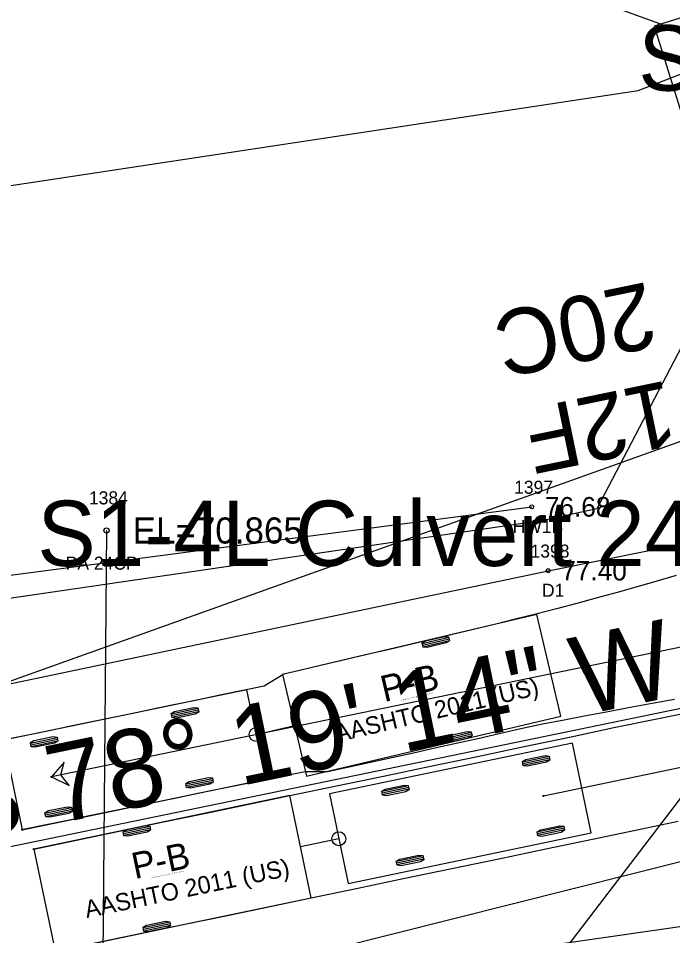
# Model space of a CAD drawing. Extents: x 2500794 to 2511032, y 910653 to 917533.
# Drawn here: x 2506003.2 to 2506053.3, y 913947.8 to 914018.1 of the extents above; entities that cross this region are included whole.
import ezdxf

# ---------------------------------------------------------------- set-up
doc = ezdxf.new("R2010")
doc.units = 0
for name, color, linetype in [('Default', 7, 'Continuous'), ('RD_EX_Bridge', 7, 'Continuous'), ('RD_EX_Bridge_txCode', 7, 'Continuous'), ('RD_EX_DR_Pipe', 7, 'Continuous'), ('RD_EX_DR_Pipe_txCode', 7, 'Continuous'), ('RD_EX_Driveway', 7, 'Continuous'), ('RD_EX_Driveway_txCode', 7, 'Continuous'), ('RD_EX_H2O', 7, 'Continuous'), ('RD_EX_H2O_txCode', 7, 'Continuous'), ('RD_EX_RW', 7, 'Continuous'), ('RD_EX_TX_Bridge_ELEV', 7, 'Continuous'), ('RD_EX_TX_Driveway_ELEV', 7, 'Continuous'), ('RD_EX_Wall', 7, 'Continuous'), ('RD_HC_Cl', 7, 'Continuous'), ('RD_HC_CL_Rel', 7, 'Continuous'), ('RD_HC_Data', 7, 'Continuous'), ('RD_HC_Data_Rel', 7, 'Continuous'), ('RD_PD_ALT1_TnTmp', 7, 'Continuous'), ('RD_PD_CstnLmt', 7, 'Continuous'), ('RD_PD_Detour', 7, 'Continuous'), ('RD_PD_Signals', 7, 'Continuous'), ('RD_SMD_Locator', 7, 'Continuous'), ('RD_TX_Pipe_ElevEX', 7, 'Continuous')]:
    doc.layers.add(name, color=color, linetype=linetype)

# ---------------------------------------------------------------- blocks, each defined once
blk = doc.blocks.new('POINT_DISPLAY')
at = {"layer": 'Default'}
blk.add_line((0, 0), (0, 0), dxfattribs=at)
blk = doc.blocks.new('Non-Wetland Waters (Tributaries)')
at = {"layer": 'Default'}
blk.add_lwpolyline([(636463.424, 232143.109), (636471.33, 232152.976), (636485.289, 232157.041), (636505.816, 232154.48), (636536.861, 232159.182), (636555.919, 232166.539), (636568.556, 232167.887)], dxfattribs=at)

msp = doc.modelspace()

# ---------------------------------------------------------------- linework, layer by layer
at = {"layer": 'RD_EX_Bridge'}
msp.add_line((2505983.467, 913972.927), (2506042.488, 913980.668), dxfattribs=at)
at = {"layer": 'RD_EX_DR_Pipe'}
msp.add_line((2506009.966, 913978.856), (2506009.594, 913936.08), dxfattribs=at)
at = {"layer": 'RD_EX_Driveway'}
for points in [[(2505985.767, 913963.589), (2506043.743, 913975.78), (2506109.597, 913989.049), (2506154.744, 914000.103)], [(2505819.536, 913956.764), (2505827.101, 913947.153), (2505840.353, 913935.262), (2505856.8, 913926.646), (2505912.429, 913930.556), (2505969.914, 913935.823), (2505992.802, 913939.066), (2506008.732, 913942.163), (2506105.494, 913966.503), (2506122.823, 913958.193)]]:
    msp.add_lwpolyline(points, dxfattribs=at)
at = {"layer": 'RD_EX_H2O_txCode'}
msp.add_lwpolyline([(2506111.845, 914025.213), (2506082.658, 914001.573), (2506056.908, 913998.584), (2506047.477, 913980.517), (2506043.365, 913979.626), (2505982.098, 913970.667), (2505951.963, 913982.389), (2505905.399, 913993.612), (2505873.017, 913999.745), (2505829.005, 914001.534), (2505817.694, 913986.507)], dxfattribs=at)
at = {"layer": 'RD_EX_RW'}
msp.add_line((2505954.669, 913828.579), (2506112.584, 914035.129), dxfattribs=at)
at = {"layer": 'RD_EX_Wall'}
msp.add_arc((2507719.022, 915869.797), 2585.05, 222.300975, 230.186861, dxfattribs=at)
at = {"layer": 'RD_HC_Cl'}
for p, q in [((2506112.069, 914036.227), (2506051.852, 914017.459)), ((2506172.262, 913989.702), (2505988.173, 913951.648))]:
    msp.add_line(p, q, dxfattribs=at)
at = {"layer": 'RD_HC_CL_Rel'}
msp.add_line((2506065.368, 913967.605), (2505988.173, 913951.648), dxfattribs=at)
at = {"layer": 'RD_HC_Data'}
msp.add_line((2506051.852, 914017.459), (2506088.25, 913900.676), dxfattribs=at)
at = {"layer": 'RD_HC_Data_Rel'}
msp.add_line((2506102.227, 913999.458), (2505949.957, 914054.921), dxfattribs=at)
at = {"layer": 'RD_PD_ALT1_TnTmp'}
for p, q in [((2506042.879, 913972.417), (2506023.414, 913967.822)), ((2506044.717, 913964.631), (2506042.879, 913972.417)), ((2506062.361, 913971.667), (2506005.748, 913959.987)), ((2506034.109, 913970.213), (2506036.137, 913970.692)), ((2506034.139, 913970.086), (2506036.167, 913970.565)), ((2506034.169, 913969.96), (2506036.197, 913970.438)), ((2506023.414, 913967.822), (2506025.252, 913960.036)), ((2506020.702, 913966.667), (2506002.099, 913962.804)), ((2506022.125, 913959.813), (2506020.702, 913966.667)), ((2506043.389, 913958.531), (2506082.325, 913966.665)), ((2506014.915, 913964.821), (2506016.954, 913965.245)), ((2506014.941, 913964.694), (2506016.981, 913965.118)), ((2506014.967, 913964.567), (2506017.007, 913964.99)), ((2506025.252, 913960.036), (2506044.717, 913964.631)), ((2506021.413, 913963.24), (2506024.333, 913963.929)), ((2506035.828, 913962.934), (2506037.855, 913963.413)), ((2506002.099, 913962.804), (2506003.522, 913955.95)), ((2506004.144, 913962.587), (2506006.185, 913963.008)), ((2506004.171, 913962.459), (2506006.211, 913962.88)), ((2506004.197, 913962.332), (2506006.237, 913962.753)), ((2506035.858, 913962.807), (2506037.885, 913963.286)), ((2506035.887, 913962.68), (2506037.915, 913963.159)), ((2506045.61, 913962.571), (2506027.012, 913958.685)), ((2506047.042, 913955.719), (2506045.61, 913962.571)), ((2506045.61, 913962.571), (2506045.61, 913962.571)), ((2506043.822, 913961.553), (2506041.783, 913961.127)), ((2506043.849, 913961.426), (2506041.81, 913961)), ((2506043.876, 913961.298), (2506041.836, 913960.872)), ((2506016.028, 913959.457), (2506018.068, 913959.88)), ((2506025.252, 913960.036), (2506025.252, 913960.036)), ((2506003.522, 913955.95), (2506022.125, 913959.813)), ((2506016.055, 913959.329), (2506018.095, 913959.753)), ((2506016.081, 913959.202), (2506018.121, 913959.625)), ((2506033.055, 913959.304), (2506031.015, 913958.878)), ((2506033.081, 913959.177), (2506031.042, 913958.751)), ((2506023.973, 913958.561), (2506004.396, 913954.472)), ((2506025.609, 913950.73), (2506023.973, 913958.561)), ((2506023.973, 913958.561), (2506023.973, 913958.561)), ((2506027.012, 913958.685), (2506028.443, 913951.833)), ((2506033.108, 913959.049), (2506031.069, 913958.623)), ((2506005.258, 913957.222), (2506007.298, 913957.643)), ((2506005.284, 913957.094), (2506007.324, 913957.515)), ((2506005.31, 913956.967), (2506007.351, 913957.388)), ((2506003.522, 913955.95), (2506003.522, 913955.95)), ((2506013.273, 913956.193), (2506011.234, 913955.767)), ((2506013.299, 913956.066), (2506011.26, 913955.64)), ((2506013.326, 913955.938), (2506011.287, 913955.512)), ((2506028.443, 913951.833), (2506047.042, 913955.719)), ((2506044.943, 913956.19), (2506042.903, 913955.764)), ((2506044.969, 913956.063), (2506042.93, 913955.636)), ((2506044.996, 913955.935), (2506042.957, 913955.509)), ((2506027.728, 913955.259), (2506024.791, 913954.646)), ((2506004.396, 913954.472), (2506006.031, 913946.641)), ((2506034.175, 913953.941), (2506032.136, 913953.515)), ((2506034.202, 913953.813), (2506032.162, 913953.387)), ((2506034.228, 913953.686), (2506032.189, 913953.26)), ((2506006.031, 913946.641), (2506025.609, 913950.73)), ((2506014.802, 913948.872), (2506012.763, 913948.446)), ((2506014.829, 913948.745), (2506012.79, 913948.319)), ((2506014.855, 913948.617), (2506012.816, 913948.191))]:
    msp.add_line(p, q, dxfattribs=at)
for points in [[(2506053.537, 913975.423), (2506052.052, 913974.981), (2506050.547, 913974.545), (2506049.023, 913974.116), (2506047.485, 913973.693), (2506045.933, 913973.276), (2506044.37, 913972.866), (2506042.797, 913972.462), (2506041.215, 913972.063), (2506039.627, 913971.669), (2506038.032, 913971.281), (2506036.432, 913970.897), (2506034.828, 913970.516), (2506033.22, 913970.137), (2506031.609, 913969.757), (2506029.997, 913969.376), (2506028.382, 913968.995), (2506026.766, 913968.613), (2506025.149, 913968.232), (2506023.53, 913967.849), (2506022.032, 913966.946), (2506020.4, 913966.606), (2506018.768, 913966.266), (2506017.135, 913965.926), (2506015.502, 913965.587), (2506013.868, 913965.248), (2506012.234, 913964.909), (2506010.6, 913964.569), (2506008.965, 913964.23), (2506007.331, 913963.89), (2506005.696, 913963.551), (2506004.061, 913963.212), (2506002.426, 913962.872)], [(2506053.412, 913965.917), (2506051.708, 913965.608), (2506050.013, 913965.296), (2506048.327, 913964.981), (2506046.647, 913964.664), (2506044.974, 913964.344), (2506043.306, 913964.022), (2506041.653, 913963.664), (2506040.007, 913963.287), (2506038.363, 913962.914), (2506036.719, 913962.545), (2506035.077, 913962.18), (2506033.435, 913961.817), (2506031.794, 913961.457), (2506030.153, 913961.1), (2506028.513, 913960.744), (2506026.873, 913960.391), (2506025.152, 913960.389), (2506023.51, 913960.054), (2506021.87, 913959.719), (2506020.23, 913959.383), (2506018.59, 913959.048), (2506016.951, 913958.712), (2506015.312, 913958.375), (2506013.674, 913958.039), (2506012.036, 913957.702), (2506010.398, 913957.366), (2506008.761, 913957.029), (2506007.123, 913956.692), (2506005.486, 913956.355), (2506003.849, 913956.018), (2506003.522, 913955.95)], [(2506004.396, 913954.472), (2506007.658, 913955.153), (2506010.921, 913955.835), (2506014.184, 913956.517), (2506017.447, 913957.198), (2506020.71, 913957.88), (2506023.973, 913958.561), (2506027.562, 913959.311), (2506031.151, 913960.061), (2506034.741, 913960.811), (2506038.33, 913961.561), (2506041.919, 913962.31), (2506045.507, 913963.068), (2506045.507, 913963.068), (2506048.775, 913963.77), (2506052.047, 913964.449), (2506055.324, 913965.111)], [(2506009.294, 913947.322), (2506012.557, 913948.004), (2506015.82, 913948.686), (2506019.083, 913949.367), (2506022.346, 913950.049), (2506025.609, 913950.73), (2506025.609, 913950.73), (2506029.198, 913951.48), (2506032.787, 913952.23), (2506036.376, 913952.98), (2506039.966, 913953.73), (2506043.555, 913954.479), (2506047.144, 913955.229), (2506047.144, 913955.229), (2506050.416, 913955.913), (2506053.688, 913956.596)]]:
    msp.add_lwpolyline(points, dxfattribs=at)
for points in [[(2506034.177, 913969.928), (2506034.102, 913970.244), (2506034.363, 913970.407), (2506035.823, 913970.751), (2506036.129, 913970.723), (2506036.204, 913970.407), (2506035.943, 913970.244), (2506034.483, 913969.9)], [(2506014.974, 913964.535), (2506014.908, 913964.853), (2506015.174, 913965.008), (2506016.642, 913965.313), (2506016.948, 913965.277), (2506017.014, 913964.958), (2506016.748, 913964.803), (2506015.279, 913964.498)], [(2506035.895, 913962.649), (2506035.82, 913962.965), (2506036.082, 913963.128), (2506037.541, 913963.472), (2506037.848, 913963.444), (2506037.922, 913963.128), (2506037.661, 913962.965), (2506036.201, 913962.621)], [(2506004.204, 913962.3), (2506004.138, 913962.618), (2506004.404, 913962.773), (2506005.873, 913963.076), (2506006.178, 913963.039), (2506006.244, 913962.721), (2506005.978, 913962.566), (2506004.509, 913962.263)], [(2506043.816, 913961.585), (2506043.882, 913961.267), (2506043.617, 913961.111), (2506042.148, 913960.805), (2506041.843, 913960.841), (2506041.776, 913961.159), (2506042.042, 913961.314), (2506043.51, 913961.621)], [(2506005.748, 913959.987), (2506007.098, 913959.333), (2506006.482, 913960.139), (2506006.729, 913961.122)], [(2506016.088, 913959.17), (2506016.022, 913959.488), (2506016.287, 913959.644), (2506017.756, 913959.948), (2506018.062, 913959.912), (2506018.128, 913959.594), (2506017.862, 913959.438), (2506016.393, 913959.134)], [(2506033.048, 913959.336), (2506033.115, 913959.017), (2506032.849, 913958.862), (2506031.381, 913958.555), (2506031.075, 913958.591), (2506031.009, 913958.91), (2506031.274, 913959.065), (2506032.743, 913959.372)], [(2506005.317, 913956.935), (2506005.251, 913957.253), (2506005.517, 913957.408), (2506006.986, 913957.711), (2506007.291, 913957.674), (2506007.357, 913957.356), (2506007.091, 913957.201), (2506005.622, 913956.898)], [(2506013.266, 913956.225), (2506013.333, 913955.907), (2506013.067, 913955.751), (2506011.599, 913955.444), (2506011.293, 913955.481), (2506011.227, 913955.799), (2506011.492, 913955.954), (2506012.961, 913956.261)], [(2506044.936, 913956.222), (2506045.003, 913955.903), (2506044.737, 913955.748), (2506043.269, 913955.441), (2506042.963, 913955.477), (2506042.897, 913955.796), (2506043.162, 913955.951), (2506044.631, 913956.258)], [(2506034.169, 913953.972), (2506034.235, 913953.654), (2506033.969, 913953.499), (2506032.501, 913953.192), (2506032.196, 913953.228), (2506032.129, 913953.546), (2506032.395, 913953.702), (2506033.863, 913954.008)], [(2506014.796, 913948.904), (2506014.862, 913948.585), (2506014.597, 913948.43), (2506013.128, 913948.123), (2506012.823, 913948.159), (2506012.756, 913948.478), (2506013.022, 913948.633), (2506014.49, 913948.94)]]:
    msp.add_lwpolyline(points, close=True, dxfattribs=at)
for centre, radius in [((2506021.413, 913963.24), 0.533), ((2506005.748, 913959.987), 0.0417), ((2506043.389, 913958.531), 0.0417), ((2506003.522, 913955.95), 0.0417), ((2506027.728, 913955.259), 0.533), ((2506004.396, 913954.472), 0.0417)]:
    msp.add_circle(centre, radius, dxfattribs=at)
at = {"layer": 'RD_PD_Signals'}
for p, q in [((2506053.859, 913985.662), (2506001.246, 913966.844)), ((2506061.314, 913949.598), (2506006.44, 913941.717))]:
    msp.add_line(p, q, dxfattribs=at)
at = {"layer": 'RD_SMD_Locator'}
for centre, radius in [((2506042.488, 913980.668), 0.15), ((2506009.966, 913978.856), 0.2), ((2506043.743, 913975.78), 0.15)]:
    msp.add_circle(centre, radius, dxfattribs=at)

# ---------------------------------------------------------------- block references
at = {"layer": 'Default', "xscale": 3.937007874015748, "yscale": 3.937007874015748}
for name, p in [('Non-Wetland Waters (Tributaries)', (0, 0)), ('POINT_DISPLAY', (2506050.635, 914012.527)), ('POINT_DISPLAY', (2506050.635, 914012.527)), ('POINT_DISPLAY', (2506004.675, 913976.138)), ('POINT_DISPLAY', (2506004.675, 913976.138))]:
    msp.add_blockref(name, p, dxfattribs=at)
at = {"layer": 'RD_EX_H2O', "xscale": 3.937007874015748, "yscale": 3.937007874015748}
msp.add_blockref('Non-Wetland Waters (Tributaries)', (0, 0), dxfattribs=at)

# ---------------------------------------------------------------- texts
at = {"layer": 'Default'}
for s, p in [('S1-3L', (2506050.635, 914012.527)), ('S1-3L', (2506050.635, 914012.527)), ('S1-4L Culvert 24"', (2506004.675, 913976.138)), ('S1-4L Culvert 24"', (2506004.675, 913976.138))]:
    msp.add_text(s, height=5, dxfattribs=at).set_placement(p)
at = {"layer": 'RD_EX_Bridge_txCode'}
for s, p in [('1397', (2506041.142, 913981.668)), ('HW1B', (2506041.031, 913978.668))]:
    msp.add_text(s, height=1, dxfattribs=at).set_placement(p)
at = {"layer": 'RD_EX_DR_Pipe_txCode'}
for s, p in [('1384', (2506008.62, 913980.856)), ('PA 24CP', (2506006.84, 913975.856))]:
    msp.add_text(s, height=1, dxfattribs=at).set_placement(p)
at = {"layer": 'RD_EX_Driveway_txCode'}
for s, p in [('1398', (2506042.396, 913976.78)), ('D1', (2506043.27, 913973.78))]:
    msp.add_text(s, height=1, dxfattribs=at).set_placement(p)
at = {"layer": 'RD_EX_TX_Bridge_ELEV'}
msp.add_text('76.68', height=1.5, dxfattribs=at).set_placement((2506043.488, 913979.918))
at = {"layer": 'RD_EX_TX_Driveway_ELEV'}
msp.add_text('77.40', height=1.5, dxfattribs=at).set_placement((2506044.743, 913975.03))
at = {"layer": 'RD_HC_Data_Rel'}
msp.add_text('S 78%%d 19\' 14" W', height=6, rotation=11.67952, dxfattribs=at).set_placement((2505998.67, 913954.839))
at = {"layer": 'RD_PD_ALT1_TnTmp'}
for s, height, rotation, p in [('P-B', 2, 13.28226, (2506031.202, 913965.715)), ('AASHTO 2011 (US)', 1.33333, 13.28226, (2506027.598, 913962.638)), ('(c) 2014 Transoft Solutions, Inc. All rights reserved.', 0.08, 13.28226, (2506032.488, 913965.813)), ('P-B', 2, 11.79947, (2506012.126, 913952.164)), ('AASHTO 2011 (US)', 1.33333, 11.79947, (2506008.444, 913949.181)), ('(c) 2014 Transoft Solutions, Inc. All rights reserved.', 0.08, 11.79947, (2506013.414, 913952.229))]:
    msp.add_text(s, height=height, rotation=rotation, dxfattribs=at).set_placement(p)
at = {"layer": 'RD_PD_CstnLmt'}
msp.add_text('12F', height=5, rotation=191.67952, dxfattribs=at).set_placement((2506052.885, 913990.373))
at = {"layer": 'RD_PD_Detour'}
msp.add_text('12F', height=5, rotation=191.67952, dxfattribs=at).set_placement((2506052.885, 913990.373))
at = {"layer": 'RD_PD_Signals'}
msp.add_text('20C', height=5, rotation=191.67952, dxfattribs=at).set_placement((2506051.329, 913997.903))
at = {"layer": 'RD_TX_Pipe_ElevEX'}
msp.add_text('EL=70.865', height=2, dxfattribs=at).set_placement((2506011.966, 913977.856))

doc.saveas('drawing.dxf')
